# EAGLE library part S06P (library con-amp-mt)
AMP MT CONNECTOR
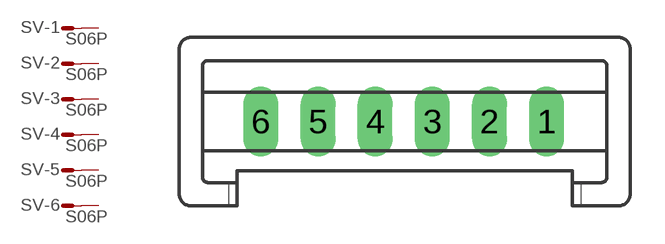
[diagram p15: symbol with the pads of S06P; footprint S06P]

Designator prefix SV; gates -1=M -2=M -3=M -4=M -5=M -6=M

## S06P (OC_FARNELL: unknown; OC_NEWARK: unknown)  [S06P]
1  -1:S  pas
2  -2:S  pas
3  -3:S  pas
4  -4:S  pas
5  -5:S  pas
6  -6:S  pas

## Footprint S06P (pad centres in mm)
AMP MT CONNECTOR
drill 1.016 long: 1 6.25,0; 2 3.75,0; 3 1.25,0; 4 -1.25,0; 5 -3.75,0; 6 -6.25,0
